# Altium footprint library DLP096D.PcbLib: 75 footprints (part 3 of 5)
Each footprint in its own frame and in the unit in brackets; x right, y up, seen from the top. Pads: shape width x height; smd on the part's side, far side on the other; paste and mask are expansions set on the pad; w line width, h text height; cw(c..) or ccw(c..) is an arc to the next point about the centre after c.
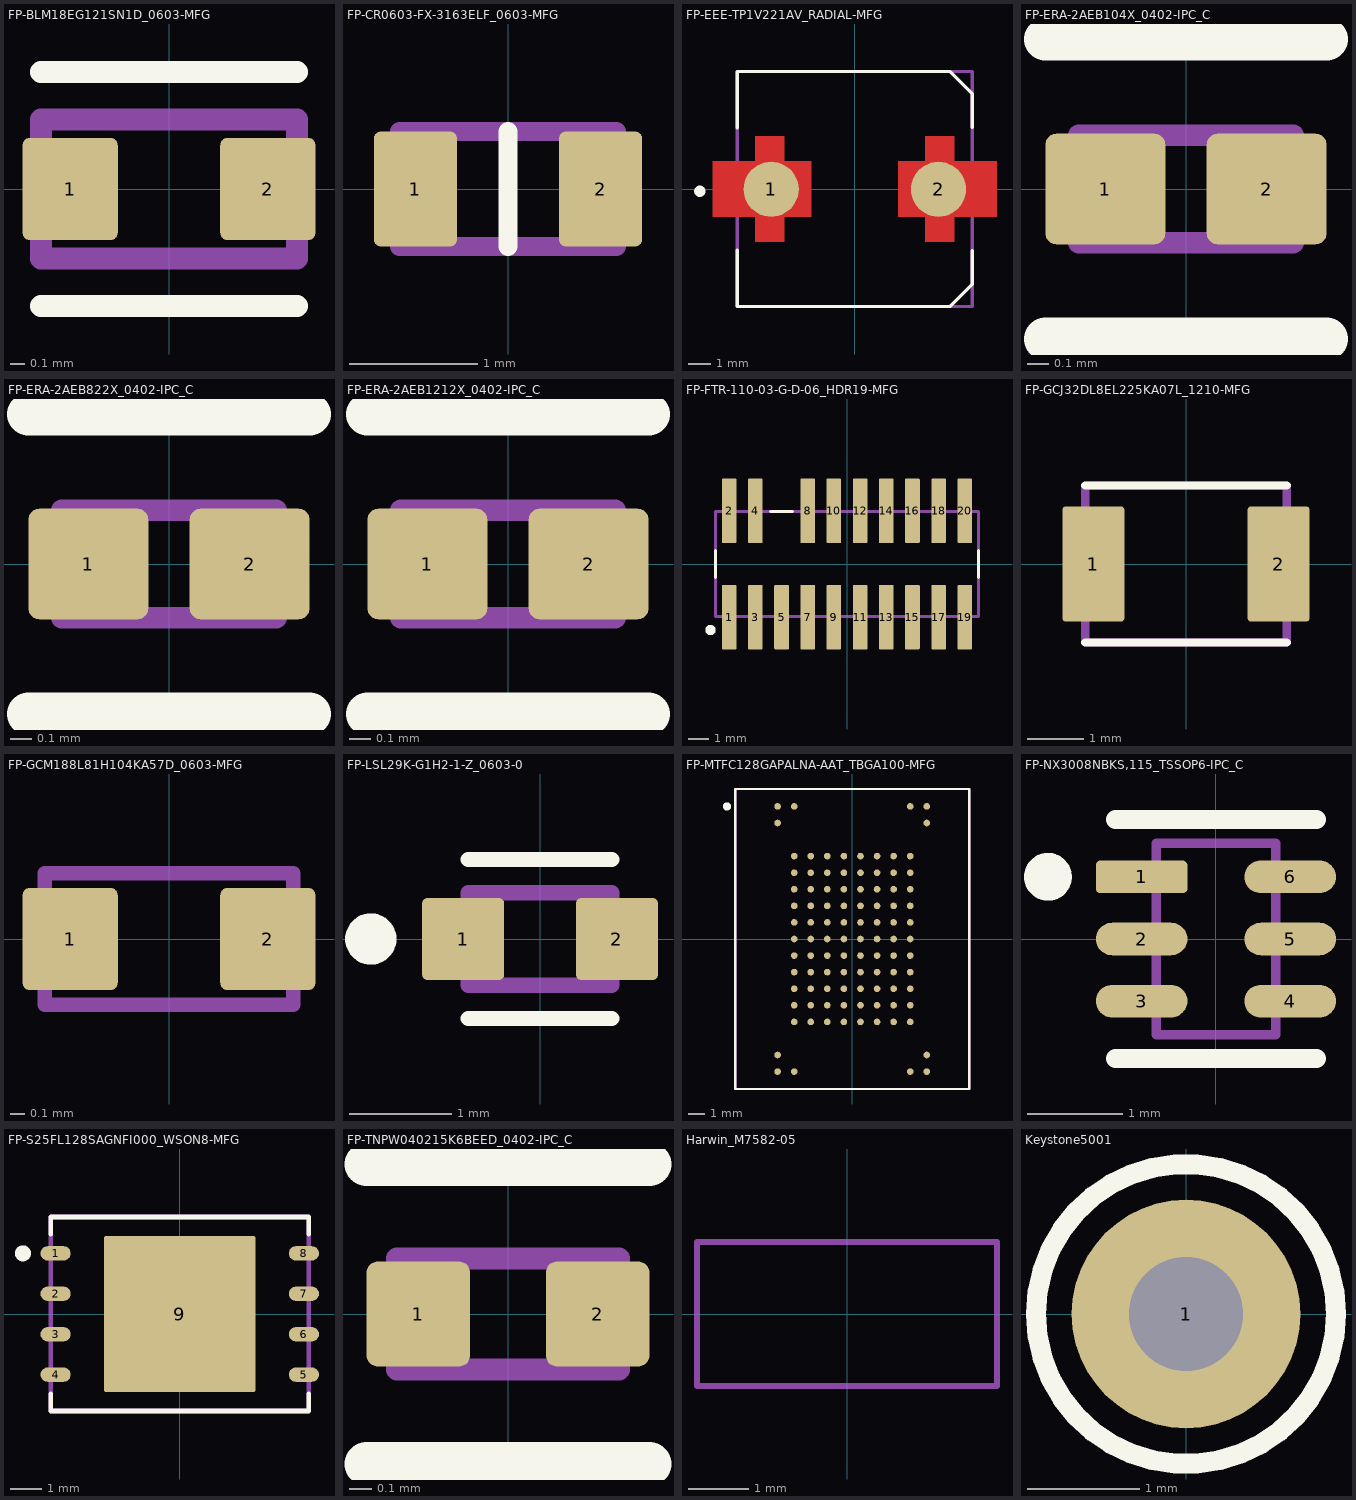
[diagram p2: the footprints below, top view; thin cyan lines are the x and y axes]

## FP-BLM18EG121SN1D_0603-MFG [mm]
pads (2):
  rrect15% 0.65x0.7 smd paste+0 mask+0: 1(-0.675,0) 2(0.675,0)
Top Overlay:
  lines w0.15: -0.875,-0.8 0.875,-0.8 ; -0.875,0.8 0.875,0.8
Mechanical 5:
  lines w0.15: -0.875,-0.475 0.875,-0.475 0.875,0.475 -0.875,0.475 -0.875,-0.475
  text ".Designator" at 0.05,0.217 h0.5
3D body "FBead_BLM18EG121SN1D_0603.STEP": height 0.25, standoff 0, extent -1.1,-0.575 1.1,0.575

## FP-CR0603-FX-3163ELF_0603-MFG [mm]
pads (2):
  rrect15% 0.65x0.9 smd paste+0 mask+0: 1(-0.725,0) 2(0.725,0)
Top Overlay:
  lines w0.15: 0,-0.45 0,0.45
Mechanical 5:
  lines w0.15: -0.85,-0.45 0.85,-0.45 0.85,0.45 -0.85,0.45 -0.85,-0.45
  text ".Designator" at 0.05,0.217 h0.5
3D body "Res_CR0603-FX-3163ELF_0603.STEP": height 0.25, standoff 0, extent -1.15,-0.55 1.15,0.55

## FP-EEE-TP1V221AV_RADIAL-MFG [mm]
pads (2):
  round 2.466 smd paste+0 mask+0: 1(-3.738,-0.012) 2(3.738,-0.012)
Top Layer:
  region: -6.35,-1.25 -6.35,1.25 -4.45,1.25 -4.45,2.35 -3.15,2.35 -3.15,1.25 -1.95,1.25 -1.95,-1.25 -3.15,-1.25 -3.15,-2.35 -4.45,-2.35 -4.45,-1.25
  region: 6.35,-1.25 6.35,1.25 4.45,1.25 4.45,2.35 3.15,2.35 3.15,1.25 1.95,1.25 1.95,-1.25 3.15,-1.25 3.15,-2.35 4.45,-2.35 4.45,-1.25
Top Overlay:
  circle w0.25: c-6.925,-0.1 r0.125
  lines w0.15: -5.25,-2.725 -5.25,-5.25 4.25,-5.25 5.25,-4.25 5.25,-2.75 ; -5.25,2.725 -5.25,5.25 4.25,5.25 5.25,4.25 5.25,2.75
Mechanical 5:
  lines w0.15: -5.25,-5.25 5.25,-5.25 5.25,5.25 -5.25,5.25 -5.25,-5.25
  text ".Designator" at 0,0 h0.5
3D body "Cap_EEE-TP1V221AV_RADIAL.STEP": height 0.25, standoff 0, extent -6.6,-5.5 6.6,5.5

## FP-ERA-2AEB104X_0402-IPC_C [mm]
pads (2):
  rrect19% 0.56x0.516 smd paste+0 mask+0: 1(-0.376,0) 2(0.376,0)
Top Overlay:
  lines w0.2: -0.656,-0.7 0.656,-0.7 ; -0.656,0.7 0.656,0.7
Mechanical 5:
  lines w0.1: -0.5,-0.25 0.5,-0.25 0.5,0.25 -0.5,0.25 -0.5,-0.25
  text ".Designator" at 0.05,0.217 h0.5
3D body "Res_ERA-2AEB104X_0402.STEP": height 0.25, standoff 0, extent -0.756,-0.4 0.756,0.4

## FP-ERA-2AEB822X_0402-IPC_C [mm]
pads (2):
  rrect19% 0.56x0.516 smd paste+0 mask+0: 1(-0.376,0) 2(0.376,0)
Top Overlay:
  lines w0.2: -0.656,-0.7 0.656,-0.7 ; -0.656,0.7 0.656,0.7
Mechanical 5:
  lines w0.1: -0.5,-0.25 0.5,-0.25 0.5,0.25 -0.5,0.25 -0.5,-0.25
  text ".Designator" at 0.05,0.217 h0.5
3D body "Res_ERA-2AEB822X_0402.STEP": height 0.25, standoff 0, extent -0.756,-0.4 0.756,0.4

## FP-ERA-2AEB1212X_0402-IPC_C [mm]
pads (2):
  rrect19% 0.56x0.516 smd paste+0 mask+0: 1(-0.376,0) 2(0.376,0)
Top Overlay:
  lines w0.2: -0.656,-0.7 0.656,-0.7 ; -0.656,0.7 0.656,0.7
Mechanical 5:
  lines w0.1: -0.5,-0.25 0.5,-0.25 0.5,0.25 -0.5,0.25 -0.5,-0.25
  text ".Designator" at 0.05,0.217 h0.5
3D body "Res_ERA-2AEB1212X_0402.STEP": height 0.25, standoff 0, extent -0.756,-0.4 0.756,0.4

## FP-FTR-110-03-G-D-06_HDR19-MFG [mil]
pads (19):
  rrect14% 28x123 smd paste+0 mask+0: 1(-225,-101.5) 2(-225,101.5) 3(-175,-101.5) 4(-175,101.5) 5(-125,-101.5) 7(-75,-101.5) 8(-75,101.5) 9(-25,-101.5) 10(-25,101.5) 11(25,-101.5) 12(25,101.5) 13(75,-101.5) 14(75,101.5) 15(125,-101.5) 16(125,101.5) 17(175,-101.5) 18(175,101.5) 19(225,-101.5) 20(225,101.5)
Top Overlay:
  circle w9.84: c-260.83,-126.11 r4.92
  lines w5.91: -250.98,-25.24 -250.98,25.24 ; -146.24,100.59 -103.76,100.59 ; 250.98,-25.24 250.98,25.24
Mechanical 5:
  lines w5.91: -250.98,-100.59 250.98,-100.59 250.98,100.59 -250.98,100.59 -250.98,-100.59
  text ".Designator" at 1.97,8.53 h19.68
3D body "Conn_FTR-110-03-G-D-06_HDR19.STEP": height 10, standoff 0, extent -254.92,-166.94 254.92,166.94

## FP-GCJ32DL8EL225KA07L_1210-MFG [mm]
pads (2):
  rrect9% 1.1x2.05 smd paste+0 mask+0: 1(-1.65,0) 2(1.65,0)
Top Overlay:
  lines w0.15: -1.8,-1.4 1.8,-1.4 ; -1.8,1.4 1.8,1.4
Mechanical 5:
  lines w0.15: -1.8,-1.4 1.8,-1.4 1.8,1.4 -1.8,1.4 -1.8,-1.4
  text ".Designator" at 0.05,0.217 h0.5
3D body "Cap_GCJ32DL8EL225KA07L_1210.STEP": height 0.25, standoff 0, extent -2.3,-1.5 2.3,1.5

## FP-GCM188L81H104KA57D_0603-MFG [mm]
pads (2):
  rrect15% 0.65x0.7 smd paste+0 mask+0: 1(-0.675,0) 2(0.675,0)
Mechanical 5:
  lines w0.1: -0.85,-0.45 0.85,-0.45 0.85,0.45 -0.85,0.45 -0.85,-0.45
  text ".Designator" at 0,0 h0.5
3D body "Cap_GCM188L81H104KA57D_0603.STEP": height 0.25, standoff 0, extent -1.1,-0.55 1.1,0.55

## FP-LSL29K-G1H2-1-Z_0603-0 [mm]
pads (2):
  rrect13% 0.8x0.8 smd paste-1000 mask+0: 1(-0.75,0) 2(0.75,0)
Top Overlay:
  circle w0.25: c-1.65,0 r0.125
  lines w0.15: -0.7,-0.775 0.7,-0.775 ; -0.7,0.775 0.7,0.775
Top Paste:
  region: -0.55,-0.35 -1.05,-0.35 -1.06,-0.35 -1.078,-0.342 -1.092,-0.328 -1.1,-0.31 -1.1,-0.3 -1.1,0.3 -1.1,0.31 -1.092,0.328 -1.078,0.342 -1.06,0.35 -1.05,0.35 -0.55,0.35 -0.54,0.35 -0.522,0.342 -0.508,0.328 -0.5,0.31 -0.5,0.3 -0.5,-0.3 -0.5,-0.31 -0.508,-0.328 -0.522,-0.342 -0.54,-0.35
  region: 1.05,0.35 1.06,0.35 1.078,0.342 1.092,0.328 1.1,0.31 1.1,0.3 1.1,-0.3 1.1,-0.31 1.092,-0.328 1.078,-0.342 1.06,-0.35 1.05,-0.35 0.55,-0.35 0.54,-0.35 0.522,-0.342 0.508,-0.328 0.5,-0.31 0.5,-0.3 0.5,0.3 0.5,0.31 0.508,0.328 0.522,0.342 0.54,0.35 0.55,0.35
Mechanical 5:
  lines w0.15: -0.7,-0.45 0.7,-0.45 0.7,0.45 -0.7,0.45 -0.7,-0.45
  text ".Designator" at 0.05,0.217 h0.5
3D body "Diode_LSL29K-G1H2-1-Z_0603.STEP": height 0.25, standoff 0, extent -1.25,-0.55 1.25,0.55

## FP-MTFC128GAPALNA-AAT_TBGA100-MFG [mm]
pads (100):
  round 0.4 smd paste+0 mask-1000: A1(-4.5,8) A2(-3.5,8) A9(3.5,8) A10(4.5,8) B1(-4.5,7) B10(4.5,7) D2(-3.5,5) D3(-2.5,5) D4(-1.5,5) D5(-0.5,5) D6(0.5,5) D7(1.5,5) D8(2.5,5) D9(3.5,5) E2(-3.5,4) E3(-2.5,4) E4(-1.5,4) E5(-0.5,4) E6(0.5,4) E7(1.5,4) E8(2.5,4) E9(3.5,4) F2(-3.5,3) F3(-2.5,3) F4(-1.5,3) F5(-0.5,3) F6(0.5,3) F7(1.5,3) F8(2.5,3) F9(3.5,3) G2(-3.5,2) G3(-2.5,2) G4(-1.5,2) G5(-0.5,2) G6(0.5,2) G7(1.5,2) G8(2.5,2) G9(3.5,2) H2(-3.5,1) H3(-2.5,1) H4(-1.5,1) H5(-0.5,1) H6(0.5,1) H7(1.5,1) H8(2.5,1) H9(3.5,1) J2(-3.5,0) J3(-2.5,0) J4(-1.5,0) J5(-0.5,0) J6(0.5,0) J7(1.5,0) J8(2.5,0) J9(3.5,0) K2(-3.5,-1) K3(-2.5,-1) K4(-1.5,-1) K5(-0.5,-1) K6(0.5,-1) K7(1.5,-1) K8(2.5,-1) K9(3.5,-1) L2(-3.5,-2) L3(-2.5,-2) L4(-1.5,-2) L5(-0.5,-2) L6(0.5,-2) L7(1.5,-2) L8(2.5,-2) L9(3.5,-2) M2(-3.5,-3) M3(-2.5,-3) M4(-1.5,-3) M5(-0.5,-3) M6(0.5,-3) M7(1.5,-3) M8(2.5,-3) M9(3.5,-3) N2(-3.5,-4) N3(-2.5,-4) N4(-1.5,-4) N5(-0.5,-4) N6(0.5,-4) N7(1.5,-4) N8(2.5,-4) N9(3.5,-4) P2(-3.5,-5) P3(-2.5,-5) P4(-1.5,-5) P5(-0.5,-5) P6(0.5,-5) P7(1.5,-5) P8(2.5,-5) P9(3.5,-5) T1(-4.5,-7) T10(4.5,-7) U1(-4.5,-8) U2(-3.5,-8) U9(3.5,-8) U10(4.5,-8)
Top Overlay:
  circle w0.25: c-7.55,8 r0.125
  lines w0.15: -7.05,-9.05 7.05,-9.05 7.05,9.05 -7.05,9.05 -7.05,-9.05
Top Solder:
  circle w0.25: c-0.5,-2 r0.125
  circle w0.25: c-2.5,-2 r0.125
  circle w0.25: c0.5,-2 r0.125
  circle w0.25: c-1.5,-2 r0.125
  circle w0.25: c3.5,-2 r0.125
  circle w0.25: c2.5,-2 r0.125
  circle w0.25: c1.5,-2 r0.125
  circle w0.25: c-3.5,-2 r0.125
  circle w0.25: c-3.5,0 r0.125
  circle w0.25: c-1.5,0 r0.125
  circle w0.25: c-2.5,0 r0.125
  circle w0.25: c-1.5,-1 r0.125
  circle w0.25: c-2.5,-1 r0.125
  circle w0.25: c-3.5,-1 r0.125
  circle w0.25: c0.5,-1 r0.125
  circle w0.25: c1.5,0 r0.125
  circle w0.25: c0.5,0 r0.125
  circle w0.25: c-0.5,0 r0.125
  circle w0.25: c1.5,-1 r0.125
  circle w0.25: c-0.5,-1 r0.125
  circle w0.25: c3.5,-1 r0.125
  circle w0.25: c2.5,1 r0.125
  circle w0.25: c3.5,0 r0.125
  circle w0.25: c3.5,2 r0.125
  circle w0.25: c3.5,1 r0.125
  circle w0.25: c2.5,2 r0.125
  circle w0.25: c2.5,0 r0.125
  circle w0.25: c2.5,-1 r0.125
  circle w0.25: c-1.5,2 r0.125
  circle w0.25: c-2.5,2 r0.125
  circle w0.25: c-3.5,2 r0.125
  circle w0.25: c-1.5,1 r0.125
  circle w0.25: c-2.5,1 r0.125
  circle w0.25: c-3.5,1 r0.125
  circle w0.25: c0.5,1 r0.125
  circle w0.25: c1.5,2 r0.125
  circle w0.25: c0.5,2 r0.125
  circle w0.25: c-0.5,2 r0.125
  circle w0.25: c1.5,1 r0.125
  circle w0.25: c-0.5,1 r0.125
  circle w0.25: c-3.5,8 r0.125
  circle w0.25: c-4.5,8 r0.125
  circle w0.25: c-2.5,4 r0.125
  circle w0.25: c-3.5,4 r0.125
  circle w0.25: c-2.5,5 r0.125
  circle w0.25: c-2.5,3 r0.125
  circle w0.25: c-3.5,5 r0.125
  circle w0.25: c-3.5,3 r0.125
  circle w0.25: c-4.5,7 r0.125
  circle w0.25: c-1.5,5 r0.125
  circle w0.25: c0.5,5 r0.125
  circle w0.25: c-0.5,5 r0.125
  circle w0.25: c0.5,3 r0.125
  circle w0.25: c0.5,4 r0.125
  circle w0.25: c-0.5,4 r0.125
  circle w0.25: c-0.5,3 r0.125
  circle w0.25: c-1.5,4 r0.125
  circle w0.25: c-1.5,3 r0.125
  circle w0.25: c3.5,4 r0.125
  circle w0.25: c2.5,4 r0.125
  circle w0.25: c1.5,4 r0.125
  circle w0.25: c3.5,3 r0.125
  circle w0.25: c2.5,3 r0.125
  circle w0.25: c1.5,3 r0.125
  circle w0.25: c3.5,8 r0.125
  circle w0.25: c2.5,5 r0.125
  circle w0.25: c4.5,8 r0.125
  circle w0.25: c4.5,7 r0.125
  circle w0.25: c3.5,5 r0.125
  circle w0.25: c1.5,5 r0.125
  circle w0.25: c-3.5,-8 r0.125
  circle w0.25: c-1.5,-5 r0.125
  circle w0.25: c-2.5,-5 r0.125
  circle w0.25: c-3.5,-5 r0.125
  circle w0.25: c-4.5,-7 r0.125
  circle w0.25: c-4.5,-8 r0.125
  circle w0.25: c2.5,-3 r0.125
  circle w0.25: c4.5,-8 r0.125
  circle w0.25: c3.5,-8 r0.125
  circle w0.25: c4.5,-7 r0.125
  circle w0.25: c3.5,-3 r0.125
  circle w0.25: c3.5,-4 r0.125
  circle w0.25: c3.5,-5 r0.125
  circle w0.25: c2.5,-4 r0.125
  circle w0.25: c2.5,-5 r0.125
  circle w0.25: c0.5,-3 r0.125
  circle w0.25: c0.5,-4 r0.125
  circle w0.25: c1.5,-4 r0.125
  circle w0.25: c-0.5,-3 r0.125
  circle w0.25: c1.5,-3 r0.125
  circle w0.25: c1.5,-5 r0.125
  circle w0.25: c0.5,-5 r0.125
  circle w0.25: c-0.5,-4 r0.125
  circle w0.25: c-0.5,-5 r0.125
  circle w0.25: c-3.5,-3 r0.125
  circle w0.25: c-1.5,-3 r0.125
  circle w0.25: c-2.5,-3 r0.125
  circle w0.25: c-1.5,-4 r0.125
  circle w0.25: c-2.5,-4 r0.125
  circle w0.25: c-3.5,-4 r0.125
Mechanical 5:
  lines w0.15: -7.05,-9.05 7.05,-9.05 7.05,9.05 -7.05,9.05 -7.05,-9.05
  text ".Designator" at 0,0 h0.5
3D body "IC_MTFC128GAPALNA-AAT_TBGA100.STEP": height 0.25, standoff 0, extent -7.55,-9.55 7.55,9.55

## FP-NX3008NBKS,115_TSSOP6-IPC_C [mm]
pads (6):
  rrect29% 0.959x0.342 smd paste+0 mask+0: 1(-0.777,0.65)
  rrect100% 0.959x0.342 smd paste+0 mask+0: 2(-0.777,0) 3(-0.777,-0.65) 4(0.777,-0.65) 5(0.777,0) 6(0.777,0.65)
Top Overlay:
  circle w0.25: c-1.756,0.65 r0.125
  lines w0.2: -1.05,-1.25 1.05,-1.25 ; -1.05,1.25 1.05,1.25
Mechanical 5:
  lines w0.1: -0.625,-1 -0.625,1 0.625,1 0.625,-1 -0.625,-1
  text ".Designator" at 0.05,0.217 h0.5
3D body "Trans_NX3008NBKS,115_TSSOP6.STEP": height 1.1, standoff 0, extent -1.05,-1 1.05,1

## FP-S25FL128SAGNFI000_WSON8-MFG [mm]
pads (9):
  rrect100% 0.95x0.45 smd paste+0 mask+0: 1(-3.9,1.905) 2(-3.9,0.635) 3(-3.9,-0.635) 4(-3.9,-1.905) 5(3.9,-1.905) 6(3.9,-0.635) 7(3.9,0.635) 8(3.9,1.905)
  rrect2% 4.75x4.9 smd paste+0 mask+0: 9(0,0)
Top Overlay:
  circle w0.25: c-4.925,1.905 r0.125
  lines w0.15: -4.05,-2.505 -4.05,-3.05 4.05,-3.05 4.05,-2.505 ; -4.05,2.505 -4.05,3.05 4.05,3.05 4.05,2.505
Mechanical 5:
  lines w0.15: -4.05,-3.05 -4.05,3.05 4.05,3.05 4.05,-3.05 -4.05,-3.05
  text ".Designator" at 0.05,0.217 h0.5
3D body "IC_S25FL128SAGNFI000_WSON8.STEP": height 0.25, standoff 0, extent -4.475,-3.226 4.475,3.226

## FP-TNPW040215K6BEED_0402-IPC_C [mm]
pads (2):
  rrect21% 0.465x0.472 smd paste+0 mask+0: 1(-0.404,0) 2(0.404,0)
Top Overlay:
  lines w0.2: -0.636,-0.675 0.636,-0.675 ; -0.636,0.675 0.636,0.675
Mechanical 5:
  lines w0.1: -0.5,-0.25 0.5,-0.25 0.5,0.25 -0.5,0.25 -0.5,-0.25
  text ".Designator" at 0.05,0.217 h0.5
3D body "Res_TNPW040215K6BEED_0402.STEP": height 0.25, standoff 0, extent -0.736,-0.375 0.736,0.375

## Harwin_M7582-05 [mm] "Single Operation 2.54mm Pitch Open Top Jumper Socket"
height 6
Mechanical 5:
  lines w0.1: -2.5,-1.2 0.7,-1.2 2.5,-1.2 2.5,1.2 0.7,1.2 -2.5,1.2 -2.5,-1.2
  text ".Designator" at -1.6,-0.4 h1.02
3D body "M7582-05.stp": height 6, standoff 0, extent -2.5,-1.2 2.5,1.2

## Keystone5001 [mil] "For Keystone 500x miniature loop terminals"
height 181.1
pads (1):
  round 80 hole 40: 1(0,0)
Top Overlay:
  circle w7: c0,0 r52.5
Mechanical 5:
  circle w3.94: c0,0 r52.5
  text ".Designator" at -92.97,-15 h18
3D body "Keystone_5001.stp": height 181.97, standoff -118.11, extent -49,-49 49.04,49.24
